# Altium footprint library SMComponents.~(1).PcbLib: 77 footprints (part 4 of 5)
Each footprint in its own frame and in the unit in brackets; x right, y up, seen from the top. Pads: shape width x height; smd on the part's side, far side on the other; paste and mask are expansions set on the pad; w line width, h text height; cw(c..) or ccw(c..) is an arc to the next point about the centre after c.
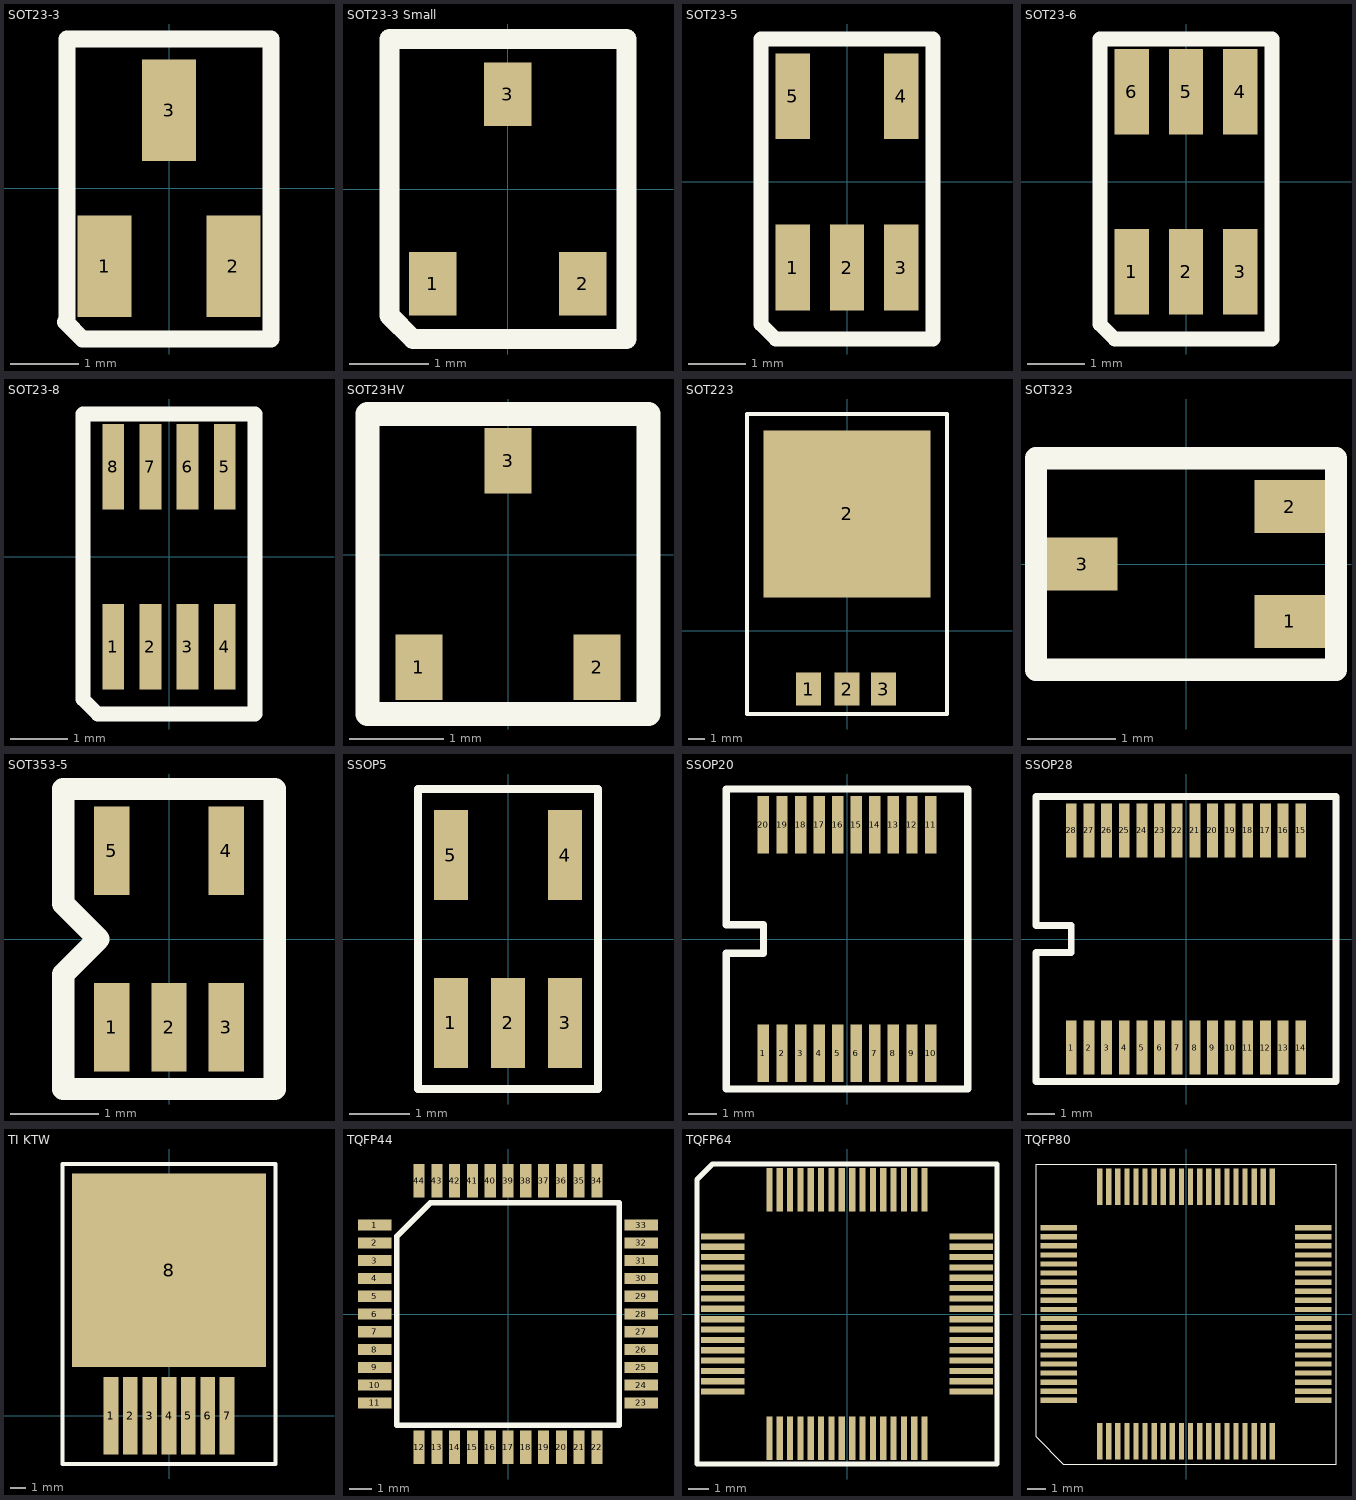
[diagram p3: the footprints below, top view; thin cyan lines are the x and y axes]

## SOT23-3 [mm] "3 pin SOT 23 with longish pads"
height 2
pads (3):
  rect 0.8x1.5 smd: 1(-0.95,-1.15) 2(0.95,-1.15) 3(0,1.15)
Top Overlay:
  lines w0.254: -1.525,-1.975 -1.275,-2.225 1.505,-2.225 1.505,2.2 -1.505,2.2 -1.505,-1.95

## SOT23-3 Small [mm] "3 pin SOT 23 with longish pads"
height 2
pads (3):
  rect 0.6x0.8 smd: 1(-0.95,-1.2) 2(0.95,-1.2) 3(0,1.2)
Top Overlay:
  lines w0.254: -1.5,-1.6 -1.2,-1.9 1.505,-1.9 1.505,1.9 -1.5,1.9 -1.5,-1.6

## SOT23-5 [mm] "% pin SOT 23 with longish pads"
height 2
pads (5):
  rect 0.6x1.5 smd: 1(-0.95,-1.5) 2(0,-1.5) 3(0.95,-1.5) 4(0.95,1.5) 5(-0.95,1.5)
Top Overlay:
  lines w0.254: -1.505,-2.495 -1.25,-2.75 1.505,-2.75 1.505,2.5 0.577,2.5 -0.928,2.5 -1.505,2.5 -1.505,-2.495

## SOT23-6 [mm] "6 pin SOT 23 with longish pads"
height 2
pads (6):
  rect 0.6x1.5 smd: 1(-0.95,-1.575) 2(0,-1.575) 3(0.95,-1.575) 4(0.95,1.575) 5(0,1.575) 6(-0.95,1.575)
Top Overlay:
  lines w0.254: -1.505,-2.495 -1.25,-2.75 1.505,-2.75 1.505,2.5 -1.505,2.5 -1.505,-2.495

## SOT23-8 [mm] "8 pin SOT 23 with longish pads"
height 2
pads (8):
  rect 0.38x1.5 smd: 1(-0.975,-1.575) 2(-0.325,-1.575) 3(0.325,-1.575) 4(0.975,-1.575) 5(0.975,1.575) 6(0.325,1.575) 7(-0.325,1.575) 8(-0.975,1.575)
Top Overlay:
  lines w0.254: -1.505,-2.495 -1.25,-2.75 -0.327,-2.75 0.327,-2.75 1.505,-2.75 1.505,2.5 0.928,2.5 0.201,2.5 -0.201,2.5 -0.577,2.5 -1.505,2.5 -1.505,-2.495

## SOT23HV [mm] "Max clearence between pads"
height 2
pads (3):
  rect 0.5x0.7 smd: 1(-0.95,-1.2) 2(0.95,-1.2) 3(0,1)
Top Overlay:
  lines w0.254: -1.5,-1.7 1.5,-1.7 1.5,1.5 -1.5,1.5 -1.5,-1.7

## SOT223 [mm] "SOT223 transistor, tab connected to pin 2, 1cm2 copper on tab"
height 2
pads (4):
  rect 1.5x2 smd: 1(-2.3,-3.5) 2(0,-3.5) 3(2.2,-3.5)
  rect 10x10 smd: 2(0,7)
Top Overlay:
  lines w0.254: -6,-5 -6,13 6,13 6,-5 -6,-5

## SOT323 [mm] "SOT323 package"
height 5
pads (3):
  rect 0.8x0.6 smd: 1(1.175,-0.65) 2(1.175,0.65) 3(-1.175,0)
Top Overlay:
  lines w0.254: -1.7,-1.2 1.7,-1.2 1.7,1.2 -1.7,1.2 -1.7,-1.2

## SOT353-5 [mm] "SOT353 five pin"
height 1.1
pads (5):
  rect 0.4x1 smd: 1(-0.65,-1) 2(0,-1) 3(0.65,-1) 4(0.65,1) 5(-0.65,1)
Top Overlay:
  lines w0.254: -1.2,-1.7 -1.2,-0.4 -0.8,0 -1.2,0.4 -1.2,1.7 1.2,1.7 1.2,-1.7 -1.2,-1.7

## SSOP5 [mm] "SSOP5 package"
height 1.524
pads (5):
  rect 0.559x1.5 smd: 1(-0.95,-1.4) 2(0,-1.4) 3(0.95,-1.4) 4(0.95,1.4) 5(-0.95,1.4)
Top Overlay:
  lines w0.127: -1.5,-2.5 -1.5,2.5 1.5,2.5 1.5,-2.5 -1.5,-2.5

## SSOP20 [mm] "SSOP 20 pin package"
height 2
pads (20):
  rect 0.4x2 smd: 1(-2.925,-4) 2(-2.275,-4) 3(-1.625,-4) 4(-0.975,-4) 5(-0.325,-4) 6(0.325,-4) 7(0.975,-4) 8(1.625,-4) 9(2.275,-4) 10(2.925,-4) 11(2.925,4) 12(2.275,4) 13(1.625,4) 14(0.975,4) 15(0.325,4) 16(-0.325,4) 17(-0.975,4) 18(-1.625,4) 19(-2.275,4) 20(-2.925,4)
Top Overlay:
  lines w0.254: -4.225,-5.25 4.225,-5.25 4.225,5.25 -4.225,5.25 -4.225,0.5 -2.925,0.5 -2.925,-0.5 -4.225,-0.5 -4.225,-5.25

## SSOP28 [mm] "SSOP 28 pin package"
height 2
pads (28):
  rect 0.4x2 smd: 1(-4.225,-4) 2(-3.575,-4) 3(-2.925,-4) 4(-2.275,-4) 5(-1.625,-4) 6(-0.975,-4) 7(-0.325,-4) 8(0.325,-4) 9(0.975,-4) 10(1.625,-4) 11(2.275,-4) 12(2.925,-4) 13(3.575,-4) 14(4.225,-4) 15(4.225,4) 16(3.575,4) 17(2.925,4) 18(2.275,4) 19(1.625,4) 20(0.975,4) 21(0.325,4) 22(-0.325,4) 23(-0.975,4) 24(-1.625,4) 25(-2.275,4) 26(-2.925,4) 27(-3.575,4) 28(-4.225,4)
Top Overlay:
  lines w0.254: -5.525,-5.25 5.525,-5.25 5.525,5.25 -5.525,5.25 -5.525,0.5 -4.225,0.5 -4.225,-0.5 -5.525,-0.5 -5.525,-5.25

## TI KTW [mil]
height 185.04
pads (8):
  rect 38x200 smd: 1(-150,0) 2(-100,0) 3(-50,0) 4(0,0) 5(50,0) 6(100,0) 7(150,0)
  rect 500x500 smd: 8(0,375)
Top Overlay:
  lines w10: -275,-125 275,-125 275,650 -275,650 -275,-125

## TQFP44 [mm] "TQFP 44"
height 1.2
pads (44):
  rect 1.5x0.5 smd: 1(-6,4) 2(-6,3.2) 3(-6,2.4) 4(-6,1.6) 5(-6,0.8) 6(-6,0) 7(-6,-0.8) 8(-6,-1.6) 9(-6,-2.4) 10(-6,-3.2) 11(-6,-4) 23(6,-4) 24(6,-3.2) 25(6,-2.4) 26(6,-1.6) 27(6,-0.8) 28(6,0) 29(6,0.8) 30(6,1.6) 31(6,2.4) 32(6,3.2) 33(6,4)
  rect 0.5x1.5 smd: 12(-4,-6) 13(-3.2,-6) 14(-2.4,-6) 15(-1.6,-6) 16(-0.8,-6) 17(0,-6) 18(0.8,-6) 19(1.6,-6) 20(2.4,-6) 21(3.2,-6) 22(4,-6) 34(4,6) 35(3.2,6) 36(2.4,6) 37(1.6,6) 38(0.8,6) 39(0,6) 40(-0.8,6) 41(-1.6,6) 42(-2.4,6) 43(-3.2,6) 44(-4,6)
Top Overlay:
  lines w0.254: -5,-5 5,-5 5,5 -3.5,5 -5,3.5 -5,-5

## TQFP64 [mm] "64 pin Thin Quad Flatpack"
height 1.2
pads (64):
  rect 2.1x0.3 smd: 1(-6,3.75) 2(-6,3.25) 3(-6,2.75) 4(-6,2.25) 5(-6,1.75) 6(-6,1.25) 7(-6,0.75) 8(-6,0.25) 9(-6,-0.25) 10(-6,-0.75) 11(-6,-1.25) 12(-6,-1.75) 13(-6,-2.25) 14(-6,-2.75) 15(-6,-3.25) 16(-6,-3.75) 33(6,-3.75) 34(6,-3.25) 35(6,-2.75) 36(6,-2.25) 37(6,-1.75) 38(6,-1.25) 39(6,-0.75) 40(6,-0.25) 41(6,0.25) 42(6,0.75) 43(6,1.25) 44(6,1.75) 45(6,2.25) 46(6,2.75) 47(6,3.25) 48(6,3.75)
  rect 0.3x2.1 smd: 17(-3.75,-6) 18(-3.25,-6) 19(-2.75,-6) 20(-2.25,-6) 21(-1.75,-6) 22(-1.25,-6) 23(-0.75,-6) 24(-0.25,-6) 25(0.25,-6) 26(0.75,-6) 27(1.25,-6) 28(1.75,-6) 29(2.25,-6) 30(2.75,-6) 31(3.25,-6) 32(3.75,-6) 49(3.75,6) 50(3.25,6) 51(2.75,6) 52(2.25,6) 53(1.75,6) 54(1.25,6) 55(0.75,6) 56(0.25,6) 57(-0.25,6) 58(-0.75,6) 59(-1.25,6) 60(-1.75,6) 61(-2.25,6) 62(-2.75,6) 63(-3.25,6) 64(-3.75,6)
Top Overlay:
  lines w0.254: -7.25,-7.25 -7.25,6.5 -6.5,7.25 7.25,7.25 7.25,-7.25 -7.25,-7.25

## TQFP80 [mm] "TQFP 80 12x12mm 0.5mm lead spacing"
height 1.2
pads (80):
  rect 0.29x2 smd: 1(-4.75,-7) 2(-4.25,-7) 3(-3.75,-7) 4(-3.25,-7) 5(-2.75,-7) 6(-2.25,-7) 7(-1.75,-7) 8(-1.25,-7) 9(-0.75,-7) 10(-0.25,-7) 11(0.25,-7) 12(0.75,-7) 13(1.25,-7) 14(1.75,-7) 15(2.25,-7) 16(2.75,-7) 17(3.25,-7) 18(3.75,-7) 19(4.25,-7) 20(4.75,-7) 41(4.75,7) 42(4.25,7) 43(3.75,7) 44(3.25,7) 45(2.75,7) 46(2.25,7) 47(1.75,7) 48(1.25,7) 49(0.75,7) 50(0.25,7) 51(-0.25,7) 52(-0.75,7) 53(-1.25,7) 54(-1.75,7) 55(-2.25,7) 56(-2.75,7) 57(-3.25,7) 58(-3.75,7) 59(-4.25,7) 60(-4.75,7)
  rect 2x0.29 smd: 21(7,-4.75) 22(7,-4.25) 23(7,-3.75) 24(7,-3.25) 25(7,-2.75) 26(7,-2.25) 27(7,-1.75) 28(7,-1.25) 29(7,-0.75) 30(7,-0.25) 31(7,0.25) 32(7,0.75) 33(7,1.25) 34(7,1.75) 35(7,2.25) 36(7,2.75) 37(7,3.25) 38(7,3.75) 39(7,4.25) 40(7,4.75) 61(-7,4.75) 62(-7,4.25) 63(-7,3.75) 64(-7,3.25) 65(-7,2.75) 66(-7,2.25) 67(-7,1.75) 68(-7,1.25) 69(-7,0.75) 70(-7,0.25) 71(-7,-0.25) 72(-7,-0.75) 73(-7,-1.25) 74(-7,-1.75) 75(-7,-2.25) 76(-7,-2.75) 77(-7,-3.25) 78(-7,-3.75) 79(-7,-4.25) 80(-7,-4.75)
Top Overlay:
  lines w0.025: -8.25,-6.75 -8.25,8.25 8.25,8.25 8.25,-8.25 -6.75,-8.25 -8.25,-6.75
